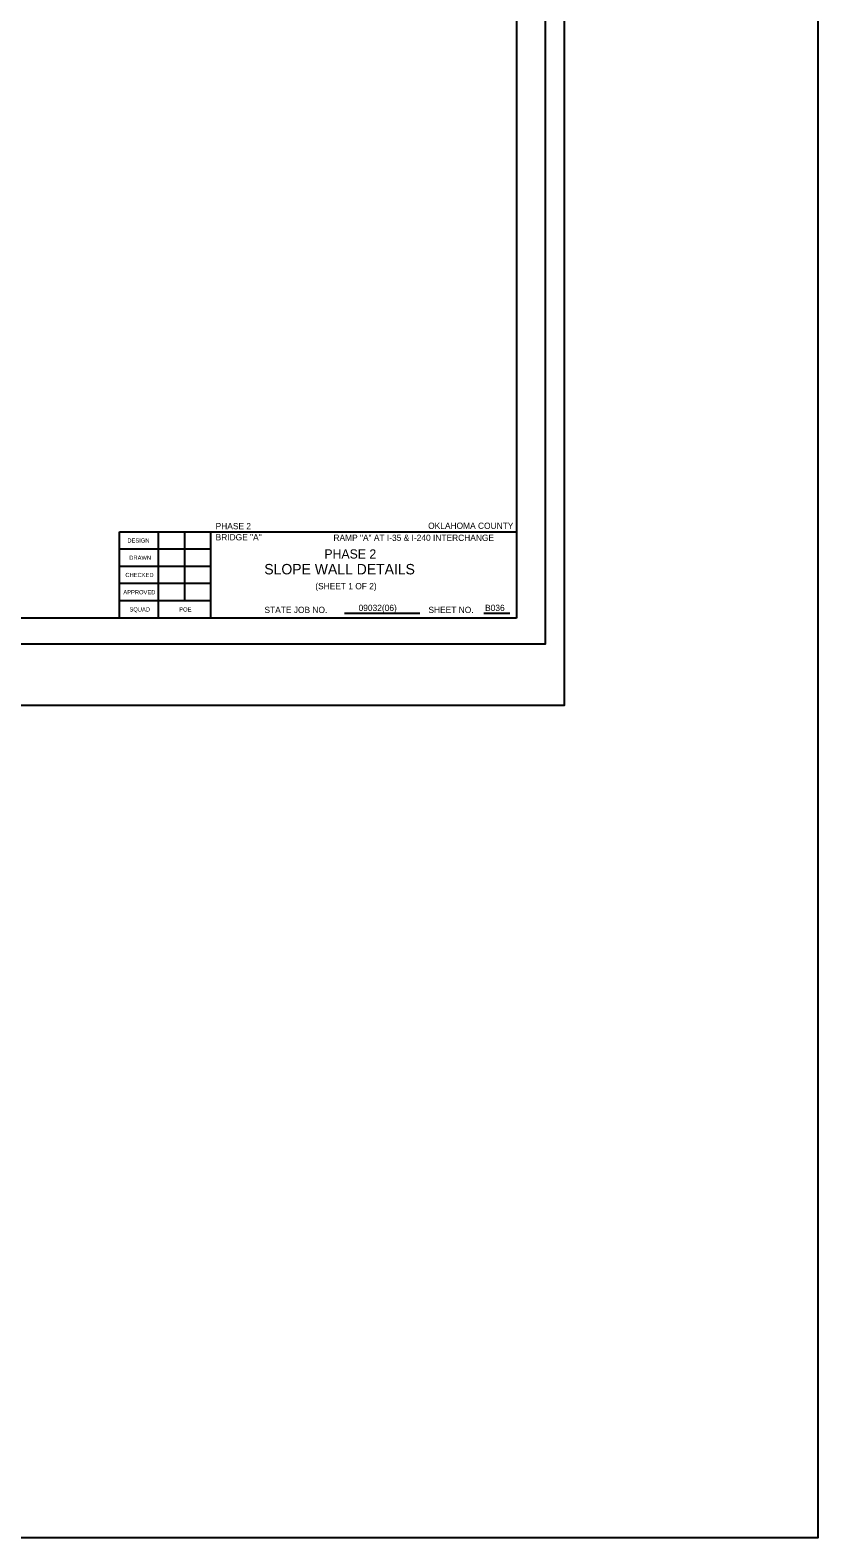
# Model space of a CAD drawing. Extents: x 570 to 2152770, y 726 to 139926.
# Drawn here: x 2151701.6 to 2151822.2, y 139264.6 to 139495.6 of the extents above; entities that cross this region are included whole.
import ezdxf

# ---------------------------------------------------------------- set-up
doc = ezdxf.new("R2010")
doc.units = 0
for name, color, linetype in [('S', 7, 'Continuous'), ('SHT_Plot_Shape_Full', 7, 'Continuous'), ('SHT_Plot_Shape_Half', 7, 'Continuous'), ('SHT_Sheet_Border', 7, 'Continuous'), ('SHT_Standard_Sheet_Lines', 7, 'Continuous'), ('SHT_Standard_Sheet_Txt', 7, 'Continuous'), ('T', 7, 'Continuous'), ('T-Title', 7, 'Continuous')]:
    doc.layers.add(name, color=color, linetype=linetype)

msp = doc.modelspace()

# ---------------------------------------------------------------- linework, layer by layer
at = {"layer": 'S'}
msp.add_lwpolyline([(2151466.83, 139693.76), (2151822.23, 139693.76), (2151822.23, 139264.64), (2151466.83, 139264.64)], close=True, dxfattribs=at)
at = {"layer": 'SHT_Plot_Shape_Full'}
msp.add_lwpolyline([(2151495.35, 139584.13), (2151783.35, 139584.13), (2151783.35, 139392.13), (2151495.35, 139392.13)], close=True, dxfattribs=at)
at = {"layer": 'SHT_Plot_Shape_Half'}
msp.add_lwpolyline([(2151508.45, 139577.53), (2151780.45, 139577.53), (2151780.45, 139401.53), (2151508.45, 139401.53)], close=True, dxfattribs=at)
at = {"layer": 'SHT_Sheet_Border'}
for p, q in [((2151715.25, 139405.53), (2151715.25, 139418.73)), ((2151715.25, 139418.73), (2151776.05, 139418.73)), ((2151729.25, 139405.53), (2151729.25, 139418.74)), ((2151729.25, 139405.53), (2151729.25, 139418.74))]:
    msp.add_line(p, q, dxfattribs=at)
msp.add_lwpolyline([(2151776.05, 139405.53), (2151524.05, 139405.53), (2151524.05, 139573.53), (2151776.05, 139573.53)], close=True, dxfattribs=at)
at = {"layer": 'SHT_Standard_Sheet_Lines'}
for p, q in [((2151721.25, 139405.53), (2151721.25, 139418.74)), ((2151725.25, 139408.17), (2151725.25, 139418.74)), ((2151749.73, 139406.3), (2151761.26, 139406.3)), ((2151749.73, 139406.3), (2151761.26, 139406.3)), ((2151771.05, 139406.3), (2151775.07, 139406.3)), ((2151771.05, 139406.3), (2151775.07, 139406.3))]:
    msp.add_line(p, q, dxfattribs=at)
for points in [[(2151729.25, 139416.09), (2151715.25, 139416.09)], [(2151729.25, 139413.45), (2151715.25, 139413.45)], [(2151729.25, 139410.81), (2151715.25, 139410.81)], [(2151729.25, 139408.17), (2151715.25, 139408.17)]]:
    msp.add_lwpolyline(points, dxfattribs=at)

# ---------------------------------------------------------------- texts
at = {"layer": 'Defpoints'}
msp.add_text('PHASE 2', height=1.406, dxfattribs=at).set_placement((2151746.64, 139414.65))
at = {"layer": 'SHT_Standard_Sheet_Txt'}
for s, height, p in [('DESIGN', 0.64, (2151716.46, 139417.09)), ('DRAWN', 0.64, (2151716.75, 139414.45)), ('CHECKED', 0.64, (2151716.15, 139411.81)), ('APPROVED', 0.64, (2151715.84, 139409.17)), ('SQUAD', 0.64, (2151716.78, 139406.53)), ('POE', 0.64, (2151724.41, 139406.53)), ('STATE JOB NO.', 0.96, (2151737.46, 139406.3)), ('STATE JOB NO.', 0.96, (2151737.46, 139406.3)), ('SHEET NO. ', 0.96, (2151762.58, 139406.3)), ('SHEET NO. ', 0.96, (2151762.58, 139406.3))]:
    msp.add_text(s, height=height, dxfattribs=at).set_placement(p)
at = {"layer": 'T'}
for s, height, p in [('PHASE 2', 0.96, (2151729.98, 139419.13)), ('OKLAHOMA COUNTY', 0.96, (2151762.54, 139419.19)), ('BRIDGE "A"', 0.96, (2151729.98, 139417.43)), ('RAMP "A" AT I-35 & I-240 INTERCHANGE', 0.96, (2151748.03, 139417.35)), ('(SHEET 1 OF 2)', 0.9583, (2151745.25, 139409.94)), ('09032(06)', 0.96, (2151751.88, 139406.61)), ('B036', 0.96, (2151771.26, 139406.61))]:
    msp.add_text(s, height=height, dxfattribs=at).set_placement(p)
at = {"layer": 'T-Title'}
msp.add_text('SLOPE WALL DETAILS', height=1.6, dxfattribs=at).set_placement((2151737.44, 139412.22))

doc.saveas('drawing.dxf')
